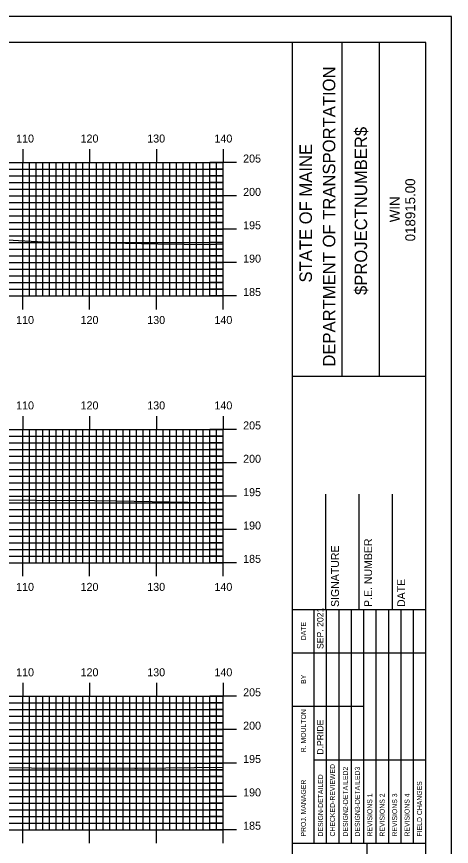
# Model space of a CAD drawing. Extents: x 1814522 to 1814865, y 442591 to 442811.
# Drawn here: x 1814796.6 to 1814861.7, y 442686.2 to 442810.5 of the extents above; entities that cross this region are included whole.
import ezdxf

# ---------------------------------------------------------------- set-up
doc = ezdxf.new("R2010")
doc.units = 0
for name, color, linetype in [('BORDER', 7, 'Continuous'), ('H_V ANNOTATION', 7, 'Continuous'), ('MAJOR', 7, 'Continuous'), ('MINOR', 7, 'Continuous'), ('PLOT BOUNDARY', 7, 'Continuous'), ('S_Roadway_Centerline', 7, 'Continuous')]:
    doc.layers.add(name, color=color, linetype=linetype)

msp = doc.modelspace()

# ---------------------------------------------------------------- linework, layer by layer
at = {"layer": 'BORDER'}
for p, q in [((1814837.91, 442596.67), (1814837.91, 442806.67)), ((1814845.36, 442756.66), (1814845.36, 442806.66)), ((1814850.95, 442756.66), (1814850.95, 442806.66)), ((1814837.91, 442756.65), (1814857.91, 442756.65)), ((1814842.91, 442721.67), (1814842.91, 442738.97)), ((1814847.91, 442721.67), (1814847.91, 442738.97)), ((1814852.91, 442721.67), (1814852.91, 442738.97)), ((1814837.91, 442721.67), (1814857.91, 442721.67)), ((1814837.91, 442686.67), (1814857.91, 442686.67)), ((1814849.09, 442616.67), (1814849.09, 442686.67))]:
    msp.add_line(p, q, dxfattribs=at)
msp.add_lwpolyline([(1814537.91, 442596.67), (1814857.91, 442596.67), (1814857.91, 442806.67), (1814537.91, 442806.67)], close=True, dxfattribs=at)
for points in [[(1814841.14, 442715.17), (1814841.14, 442721.67)], [(1814843, 442686.68), (1814843, 442721.67)], [(1814844.87, 442721.67), (1814844.87, 442686.68)], [(1814846.73, 442686.68), (1814846.73, 442721.67)], [(1814848.59, 442686.68), (1814848.59, 442721.67)], [(1814850.46, 442686.68), (1814850.46, 442721.67)], [(1814852.32, 442686.68), (1814852.32, 442721.67)], [(1814854.18, 442686.68), (1814854.18, 442721.67)], [(1814856.05, 442686.68), (1814856.05, 442721.67)], [(1814841.14, 442686.68), (1814841.14, 442720.26)], [(1814837.91, 442715.17), (1814857.91, 442715.17)], [(1814837.91, 442707.17), (1814841.14, 442707.17)], [(1814841.14, 442707.17), (1814848.59, 442707.17)], [(1814841.14, 442699.17), (1814857.91, 442699.17)]]:
    msp.add_lwpolyline(points, dxfattribs=at)
at = {"layer": 'MAJOR'}
for p, q in [((1814797.51, 442790.67), (1814797.51, 442788.67)), ((1814807.51, 442790.67), (1814807.51, 442788.67)), ((1814817.51, 442790.67), (1814817.51, 442788.67)), ((1814827.51, 442790.67), (1814827.51, 442788.67)), ((1814547.51, 442788.67), (1814827.51, 442788.67)), ((1814547.51, 442788.67), (1814827.51, 442788.67)), ((1814797.51, 442768.67), (1814797.51, 442788.67)), ((1814807.51, 442768.67), (1814807.51, 442788.67)), ((1814817.51, 442768.67), (1814817.51, 442788.67)), ((1814829.51, 442788.67), (1814825.5, 442788.67)), ((1814827.51, 442768.67), (1814827.51, 442788.67)), ((1814827.51, 442768.67), (1814827.51, 442788.67)), ((1814547.51, 442783.67), (1814827.51, 442783.67)), ((1814829.51, 442783.67), (1814825.5, 442783.67)), ((1814547.51, 442778.67), (1814827.51, 442778.67)), ((1814829.51, 442778.67), (1814825.5, 442778.67)), ((1814547.51, 442773.67), (1814827.51, 442773.67)), ((1814829.51, 442773.67), (1814825.5, 442773.67)), ((1814547.51, 442768.67), (1814827.51, 442768.67)), ((1814547.51, 442768.67), (1814827.51, 442768.67)), ((1814797.51, 442766.66), (1814797.51, 442768.67)), ((1814807.51, 442766.66), (1814807.51, 442768.67)), ((1814817.51, 442766.66), (1814817.51, 442768.67)), ((1814829.51, 442768.67), (1814825.5, 442768.67)), ((1814827.51, 442766.66), (1814827.51, 442768.67)), ((1814797.51, 442750.67), (1814797.51, 442748.67)), ((1814807.51, 442750.67), (1814807.51, 442748.67)), ((1814817.51, 442750.67), (1814817.51, 442748.67)), ((1814827.51, 442750.67), (1814827.51, 442748.67)), ((1814547.51, 442748.67), (1814827.51, 442748.67)), ((1814547.51, 442748.67), (1814827.51, 442748.67)), ((1814797.51, 442728.67), (1814797.51, 442748.67)), ((1814807.51, 442728.67), (1814807.51, 442748.67)), ((1814817.51, 442728.67), (1814817.51, 442748.67)), ((1814829.51, 442748.67), (1814825.5, 442748.67)), ((1814827.51, 442728.67), (1814827.51, 442748.67)), ((1814827.51, 442728.67), (1814827.51, 442748.67)), ((1814547.51, 442743.67), (1814827.51, 442743.67)), ((1814829.51, 442743.67), (1814825.5, 442743.67)), ((1814547.51, 442738.67), (1814827.51, 442738.67)), ((1814829.51, 442738.67), (1814825.5, 442738.67)), ((1814547.51, 442733.67), (1814827.51, 442733.67)), ((1814829.51, 442733.67), (1814825.5, 442733.67)), ((1814547.51, 442728.67), (1814827.51, 442728.67)), ((1814547.51, 442728.67), (1814827.51, 442728.67)), ((1814797.51, 442726.66), (1814797.51, 442728.67)), ((1814807.51, 442726.66), (1814807.51, 442728.67)), ((1814817.51, 442726.66), (1814817.51, 442728.67)), ((1814829.51, 442728.67), (1814825.5, 442728.67)), ((1814827.51, 442726.66), (1814827.51, 442728.67)), ((1814797.51, 442710.67), (1814797.51, 442708.67)), ((1814807.51, 442710.67), (1814807.51, 442708.67)), ((1814817.51, 442710.67), (1814817.51, 442708.67)), ((1814827.51, 442710.67), (1814827.51, 442708.67)), ((1814547.51, 442708.67), (1814827.51, 442708.67)), ((1814547.51, 442708.67), (1814827.51, 442708.67)), ((1814797.51, 442688.67), (1814797.51, 442708.67)), ((1814807.51, 442688.67), (1814807.51, 442708.67)), ((1814817.51, 442688.67), (1814817.51, 442708.67)), ((1814829.51, 442708.67), (1814825.5, 442708.67)), ((1814827.51, 442688.67), (1814827.51, 442708.67)), ((1814827.51, 442688.67), (1814827.51, 442708.67)), ((1814547.51, 442703.67), (1814827.51, 442703.67)), ((1814829.51, 442703.67), (1814825.5, 442703.67)), ((1814547.51, 442698.67), (1814827.51, 442698.67)), ((1814829.51, 442698.67), (1814825.5, 442698.67)), ((1814547.51, 442693.67), (1814827.51, 442693.67)), ((1814829.51, 442693.67), (1814825.5, 442693.67)), ((1814547.51, 442688.67), (1814827.51, 442688.67)), ((1814547.51, 442688.67), (1814827.51, 442688.67)), ((1814797.51, 442686.66), (1814797.51, 442688.67)), ((1814807.51, 442686.66), (1814807.51, 442688.67)), ((1814817.51, 442686.66), (1814817.51, 442688.67)), ((1814829.51, 442688.67), (1814825.5, 442688.67)), ((1814827.51, 442686.66), (1814827.51, 442688.67))]:
    msp.add_line(p, q, dxfattribs=at)
at = {"layer": 'MINOR'}
for p, q in [((1814798.51, 442768.67), (1814798.51, 442788.67)), ((1814799.51, 442768.67), (1814799.51, 442788.67)), ((1814800.51, 442768.67), (1814800.51, 442788.67)), ((1814801.51, 442768.67), (1814801.51, 442788.67)), ((1814802.51, 442768.67), (1814802.51, 442788.67)), ((1814803.51, 442768.67), (1814803.51, 442788.67)), ((1814804.51, 442768.67), (1814804.51, 442788.67)), ((1814805.51, 442768.67), (1814805.51, 442788.67)), ((1814806.51, 442768.67), (1814806.51, 442788.67)), ((1814808.51, 442768.67), (1814808.51, 442788.67)), ((1814809.51, 442768.67), (1814809.51, 442788.67)), ((1814810.51, 442768.67), (1814810.51, 442788.67)), ((1814811.51, 442768.67), (1814811.51, 442788.67)), ((1814812.51, 442768.67), (1814812.51, 442788.67)), ((1814813.51, 442768.67), (1814813.51, 442788.67)), ((1814814.51, 442768.67), (1814814.51, 442788.67)), ((1814815.51, 442768.67), (1814815.51, 442788.67)), ((1814816.51, 442768.67), (1814816.51, 442788.67)), ((1814818.51, 442768.67), (1814818.51, 442788.67)), ((1814819.51, 442768.67), (1814819.51, 442788.67)), ((1814820.51, 442768.67), (1814820.51, 442788.67)), ((1814821.51, 442768.67), (1814821.51, 442788.67)), ((1814822.51, 442768.67), (1814822.51, 442788.67)), ((1814823.51, 442768.67), (1814823.51, 442788.67)), ((1814824.51, 442768.67), (1814824.51, 442788.67)), ((1814825.51, 442768.67), (1814825.51, 442788.67)), ((1814826.51, 442768.67), (1814826.51, 442788.67)), ((1814547.51, 442787.67), (1814827.51, 442787.67)), ((1814547.51, 442786.67), (1814827.51, 442786.67)), ((1814827.51, 442787.67), (1814825.5, 442787.67)), ((1814827.51, 442786.67), (1814825.5, 442786.67)), ((1814547.51, 442785.67), (1814827.51, 442785.67)), ((1814827.51, 442785.67), (1814825.5, 442785.67)), ((1814547.51, 442784.67), (1814827.51, 442784.67)), ((1814827.51, 442784.67), (1814825.5, 442784.67)), ((1814547.51, 442782.67), (1814827.51, 442782.67)), ((1814547.51, 442781.67), (1814827.51, 442781.67)), ((1814827.51, 442782.67), (1814825.5, 442782.67)), ((1814827.51, 442781.67), (1814825.5, 442781.67)), ((1814547.51, 442780.67), (1814827.51, 442780.67)), ((1814827.51, 442780.67), (1814825.5, 442780.67)), ((1814547.51, 442779.67), (1814827.51, 442779.67)), ((1814827.51, 442779.67), (1814825.5, 442779.67)), ((1814547.51, 442777.67), (1814827.51, 442777.67)), ((1814827.51, 442777.67), (1814825.5, 442777.67)), ((1814547.51, 442776.67), (1814827.51, 442776.67)), ((1814547.51, 442775.67), (1814827.51, 442775.67)), ((1814827.51, 442776.67), (1814825.5, 442776.67)), ((1814827.51, 442775.67), (1814825.5, 442775.67)), ((1814547.51, 442774.67), (1814827.51, 442774.67)), ((1814827.51, 442774.67), (1814825.5, 442774.67)), ((1814547.51, 442772.67), (1814827.51, 442772.67)), ((1814827.51, 442772.67), (1814825.5, 442772.67)), ((1814547.51, 442771.67), (1814827.51, 442771.67)), ((1814547.51, 442770.67), (1814827.51, 442770.67)), ((1814827.51, 442771.67), (1814825.5, 442771.67)), ((1814827.51, 442770.67), (1814825.5, 442770.67)), ((1814547.51, 442769.67), (1814827.51, 442769.67)), ((1814827.51, 442769.67), (1814825.5, 442769.67)), ((1814798.51, 442728.67), (1814798.51, 442748.67)), ((1814799.51, 442728.67), (1814799.51, 442748.67)), ((1814800.51, 442728.67), (1814800.51, 442748.67)), ((1814801.51, 442728.67), (1814801.51, 442748.67)), ((1814802.51, 442728.67), (1814802.51, 442748.67)), ((1814803.51, 442728.67), (1814803.51, 442748.67)), ((1814804.51, 442728.67), (1814804.51, 442748.67)), ((1814805.51, 442728.67), (1814805.51, 442748.67)), ((1814806.51, 442728.67), (1814806.51, 442748.67)), ((1814808.51, 442728.67), (1814808.51, 442748.67)), ((1814809.51, 442728.67), (1814809.51, 442748.67)), ((1814810.51, 442728.67), (1814810.51, 442748.67)), ((1814811.51, 442728.67), (1814811.51, 442748.67)), ((1814812.51, 442728.67), (1814812.51, 442748.67)), ((1814813.51, 442728.67), (1814813.51, 442748.67)), ((1814814.51, 442728.67), (1814814.51, 442748.67)), ((1814815.51, 442728.67), (1814815.51, 442748.67)), ((1814816.51, 442728.67), (1814816.51, 442748.67)), ((1814818.51, 442728.67), (1814818.51, 442748.67)), ((1814819.51, 442728.67), (1814819.51, 442748.67)), ((1814820.51, 442728.67), (1814820.51, 442748.67)), ((1814821.51, 442728.67), (1814821.51, 442748.67)), ((1814822.51, 442728.67), (1814822.51, 442748.67)), ((1814823.51, 442728.67), (1814823.51, 442748.67)), ((1814824.51, 442728.67), (1814824.51, 442748.67)), ((1814825.51, 442728.67), (1814825.51, 442748.67)), ((1814826.51, 442728.67), (1814826.51, 442748.67)), ((1814547.51, 442747.67), (1814827.51, 442747.67)), ((1814827.51, 442747.67), (1814825.5, 442747.67)), ((1814547.51, 442746.67), (1814827.51, 442746.67)), ((1814547.51, 442745.67), (1814827.51, 442745.67)), ((1814827.51, 442746.67), (1814825.5, 442746.67)), ((1814827.51, 442745.67), (1814825.5, 442745.67)), ((1814547.51, 442744.67), (1814827.51, 442744.67)), ((1814827.51, 442744.67), (1814825.5, 442744.67)), ((1814547.51, 442742.67), (1814827.51, 442742.67)), ((1814827.51, 442742.67), (1814825.5, 442742.67)), ((1814547.51, 442741.67), (1814827.51, 442741.67)), ((1814547.51, 442740.67), (1814827.51, 442740.67)), ((1814827.51, 442741.67), (1814825.5, 442741.67)), ((1814827.51, 442740.67), (1814825.5, 442740.67)), ((1814547.51, 442739.67), (1814827.51, 442739.67)), ((1814827.51, 442739.67), (1814825.5, 442739.67)), ((1814547.51, 442737.67), (1814827.51, 442737.67)), ((1814827.51, 442737.67), (1814825.5, 442737.67)), ((1814547.51, 442736.67), (1814827.51, 442736.67)), ((1814547.51, 442735.67), (1814827.51, 442735.67)), ((1814827.51, 442736.67), (1814825.5, 442736.67)), ((1814827.51, 442735.67), (1814825.5, 442735.67)), ((1814547.51, 442734.67), (1814827.51, 442734.67)), ((1814827.51, 442734.67), (1814825.5, 442734.67)), ((1814547.51, 442732.67), (1814827.51, 442732.67)), ((1814827.51, 442732.67), (1814825.5, 442732.67)), ((1814547.51, 442731.67), (1814827.51, 442731.67)), ((1814547.51, 442730.67), (1814827.51, 442730.67)), ((1814827.51, 442731.67), (1814825.5, 442731.67)), ((1814827.51, 442730.67), (1814825.5, 442730.67)), ((1814547.51, 442729.67), (1814827.51, 442729.67)), ((1814827.51, 442729.67), (1814825.5, 442729.67)), ((1814798.51, 442688.67), (1814798.51, 442708.67)), ((1814799.51, 442688.67), (1814799.51, 442708.67)), ((1814800.51, 442688.67), (1814800.51, 442708.67)), ((1814801.51, 442688.67), (1814801.51, 442708.67)), ((1814802.51, 442688.67), (1814802.51, 442708.67)), ((1814803.51, 442688.67), (1814803.51, 442708.67)), ((1814804.51, 442688.67), (1814804.51, 442708.67)), ((1814805.51, 442688.67), (1814805.51, 442708.67)), ((1814806.51, 442688.67), (1814806.51, 442708.67)), ((1814808.51, 442688.67), (1814808.51, 442708.67)), ((1814809.51, 442688.67), (1814809.51, 442708.67)), ((1814810.51, 442688.67), (1814810.51, 442708.67)), ((1814811.51, 442688.67), (1814811.51, 442708.67)), ((1814812.51, 442688.67), (1814812.51, 442708.67)), ((1814813.51, 442688.67), (1814813.51, 442708.67)), ((1814814.51, 442688.67), (1814814.51, 442708.67)), ((1814815.51, 442688.67), (1814815.51, 442708.67)), ((1814816.51, 442688.67), (1814816.51, 442708.67)), ((1814818.51, 442688.67), (1814818.51, 442708.67)), ((1814819.51, 442688.67), (1814819.51, 442708.67)), ((1814820.51, 442688.67), (1814820.51, 442708.67)), ((1814821.51, 442688.67), (1814821.51, 442708.67)), ((1814822.51, 442688.67), (1814822.51, 442708.67)), ((1814823.51, 442688.67), (1814823.51, 442708.67)), ((1814824.51, 442688.67), (1814824.51, 442708.67)), ((1814825.51, 442688.67), (1814825.51, 442708.67)), ((1814826.51, 442688.67), (1814826.51, 442708.67)), ((1814547.51, 442707.67), (1814827.51, 442707.67)), ((1814827.51, 442707.67), (1814825.5, 442707.67)), ((1814547.51, 442706.67), (1814827.51, 442706.67)), ((1814827.51, 442706.67), (1814825.5, 442706.67)), ((1814547.51, 442705.67), (1814827.51, 442705.67)), ((1814547.51, 442704.67), (1814827.51, 442704.67)), ((1814827.51, 442705.67), (1814825.5, 442705.67)), ((1814827.51, 442704.67), (1814825.5, 442704.67)), ((1814547.51, 442702.67), (1814827.51, 442702.67)), ((1814827.51, 442702.67), (1814825.5, 442702.67)), ((1814547.51, 442701.67), (1814827.51, 442701.67)), ((1814827.51, 442701.67), (1814825.5, 442701.67)), ((1814547.51, 442700.67), (1814827.51, 442700.67)), ((1814547.51, 442699.67), (1814827.51, 442699.67)), ((1814827.51, 442700.67), (1814825.5, 442700.67)), ((1814827.51, 442699.67), (1814825.5, 442699.67)), ((1814547.51, 442697.67), (1814827.51, 442697.67)), ((1814827.51, 442697.67), (1814825.5, 442697.67)), ((1814547.51, 442696.67), (1814827.51, 442696.67)), ((1814827.51, 442696.67), (1814825.5, 442696.67)), ((1814547.51, 442695.67), (1814827.51, 442695.67)), ((1814547.51, 442694.67), (1814827.51, 442694.67)), ((1814827.51, 442695.67), (1814825.5, 442695.67)), ((1814827.51, 442694.67), (1814825.5, 442694.67)), ((1814547.51, 442692.67), (1814827.51, 442692.67)), ((1814827.51, 442692.67), (1814825.5, 442692.67)), ((1814547.51, 442691.67), (1814827.51, 442691.67)), ((1814827.51, 442691.67), (1814825.5, 442691.67)), ((1814547.51, 442690.67), (1814827.51, 442690.67)), ((1814547.51, 442689.67), (1814827.51, 442689.67)), ((1814827.51, 442690.67), (1814825.5, 442690.67)), ((1814827.51, 442689.67), (1814825.5, 442689.67))]:
    msp.add_line(p, q, dxfattribs=at)
at = {"layer": 'PLOT BOUNDARY'}
msp.add_lwpolyline([(1814521.72, 442590.55), (1814861.72, 442590.55), (1814861.72, 442810.55), (1814521.72, 442810.55)], close=True, dxfattribs=at)
at = {"layer": 'S_Roadway_Centerline'}
for points in [[(1814726.3, 442778.47), (1814734.13, 442778.67), (1814739.24, 442778.72), (1814751.28, 442777.78), (1814768.47, 442777.95), (1814769.28, 442777.93), (1814769.86, 442777.9), (1814773.96, 442777.89), (1814784.69, 442777.72), (1814796.83, 442776.97), (1814800.62, 442776.8), (1814805.61, 442776.74), (1814817.72, 442776.47), (1814825.64, 442776.39), (1814827.51, 442776.49)], [(1814732.24, 442738.99), (1814742.09, 442738.73), (1814745.21, 442739.15), (1814751.27, 442738.99), (1814758.19, 442738.73), (1814760.89, 442738.67), (1814788.1, 442738.15), (1814790.2, 442738.11), (1814790.67, 442738.11), (1814808.22, 442738.04), (1814811.48, 442737.99), (1814824.94, 442737.73), (1814827.51, 442737.68)], [(1814730.18, 442699.25), (1814739.58, 442699.13), (1814747.15, 442699.03), (1814752.1, 442698.84), (1814763.32, 442698.18), (1814768.29, 442698.26), (1814780.81, 442698.03), (1814783.25, 442698.01), (1814814.29, 442697.92), (1814814.36, 442697.92), (1814814.62, 442697.92), (1814827.51, 442698.04)]]:
    msp.add_lwpolyline(points, dxfattribs=at)

# ---------------------------------------------------------------- texts
at = {"layer": 'BORDER'}
for s, height, p in [('DEPARTMENT OF TRANSPORTATION', 1.8635, (1814844.32, 442758.08)), ('$PROJECTNUMBER$', 1.8635, (1814849.09, 442768.82)), ('STATE OF MAINE', 1.8635, (1814840.82, 442770.69)), ('018915.00', 1.491, (1814856.3, 442776.86)), ('WIN', 1.491, (1814853.98, 442779.73)), ('P.E. NUMBER', 1.1811, (1814849.83, 442722.06)), ('SIGNATURE', 1.181, (1814844.87, 442722.06)), ('DATE', 1.181, (1814854.79, 442722.06)), ('SEP. 2021', 0.969, (1814842.55, 442715.76)), ('DATE', 0.743, (1814839.92, 442717.08)), ('BY', 0.743, (1814839.92, 442710.54)), ('R. MOULTON', 0.745, (1814839.92, 442700.28)), ('D.PRIDE', 0.969, (1814842.55, 442699.92)), ('CHECKED-REVIEWED', 0.7455, (1814844.27, 442687.65)), ('DESIGN2-DETAILED2', 0.7455, (1814846.21, 442687.65)), ('DESIGN3-DETAILED3', 0.7455, (1814848, 442687.65)), ('PROJ. MANAGER', 0.7455, (1814839.92, 442687.65)), ('DESIGN-DETAILED', 0.7455, (1814842.48, 442687.65)), ('FIELD CHANGES', 0.7455, (1814857.31, 442687.65)), ('REVISIONS 1', 0.7455, (1814849.86, 442687.65)), ('REVISIONS 2', 0.7455, (1814851.72, 442687.65)), ('REVISIONS 3', 0.7455, (1814853.59, 442687.65)), ('REVISIONS 4', 0.7455, (1814855.45, 442687.65))]:
    msp.add_text(s, height=height, rotation=90, dxfattribs=at).set_placement(p)
at = {"layer": 'H_V ANNOTATION'}
for s, p in [('110', (1814796.49, 442791.67)), ('120', (1814806.15, 442791.67)), ('130', (1814816.14, 442791.67)), ('140', (1814826.21, 442791.67)), ('205', (1814830.51, 442788.67)), ('200', (1814830.51, 442783.67)), ('195', (1814830.51, 442778.67)), ('190', (1814830.51, 442773.67)), ('185', (1814830.51, 442768.67)), ('110', (1814796.49, 442764.47)), ('120', (1814806.15, 442764.47)), ('130', (1814816.14, 442764.47)), ('140', (1814826.21, 442764.47)), ('110', (1814796.49, 442751.67)), ('120', (1814806.15, 442751.67)), ('130', (1814816.14, 442751.67)), ('140', (1814826.21, 442751.67)), ('205', (1814830.51, 442748.67)), ('200', (1814830.51, 442743.67)), ('195', (1814830.51, 442738.67)), ('190', (1814830.51, 442733.67)), ('185', (1814830.51, 442728.67)), ('110', (1814796.49, 442724.47)), ('120', (1814806.15, 442724.47)), ('130', (1814816.14, 442724.47)), ('140', (1814826.21, 442724.47)), ('110', (1814796.49, 442711.67)), ('120', (1814806.15, 442711.67)), ('130', (1814816.14, 442711.67)), ('140', (1814826.21, 442711.67)), ('205', (1814830.51, 442708.67)), ('200', (1814830.51, 442703.67)), ('195', (1814830.51, 442698.67)), ('190', (1814830.51, 442693.67)), ('185', (1814830.51, 442688.67))]:
    msp.add_text(s, height=1.2, dxfattribs=at).set_placement(p)

doc.saveas('drawing.dxf')
